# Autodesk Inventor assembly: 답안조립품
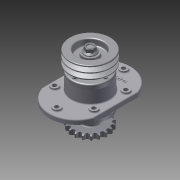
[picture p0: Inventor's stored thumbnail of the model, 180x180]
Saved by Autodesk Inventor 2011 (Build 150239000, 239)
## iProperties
Created: 2015-02
Part Number: 답안조립품
Document SubType Name: Assembly
Designer: Administrator
Author: Administrator
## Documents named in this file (11)
- C:\Documents and Settings\Administrator\바탕 화면\450207V1010\답안조립품.iam
- C:\Documents and Settings\Administrator\바탕 화면\450207V1010\본체.ipt
- C:\Documents and Settings\Administrator\바탕 화면\450207V1010\2-커버.ipt
- C:\Documents and Settings\Administrator\바탕 화면\450207V1010\3-축.ipt
- C:\Documents and Settings\Administrator\바탕 화면\450207V1010\11-키 6x6.ipt
- C:\Documents and Settings\Administrator\바탕 화면\450207V1010\4-V벨트풀리.ipt
- C:\Documents and Settings\Administrator\바탕 화면\450207V1010\9-M16-너트.ipt
- C:\Documents and Settings\Administrator\바탕 화면\450207V1010\5-체인 스프로킷.ipt
- C:\Documents and Settings\Administrator\바탕 화면\450207V1010\6-베어링 6206.ipt
- C:\Documents and Settings\Administrator\바탕 화면\450207V1010\10-M6.ipt
- C:\Documents and Settings\Administrator\바탕 화면\450207V1010\8-오일실 30x42.ipt
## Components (21 placed, 9 different names)
1. 2-커버:1
2. 2-커버:2
3. 3-축:1
4. 11-키 6x6:1 — 각도:3
5. 11-키 6x6:2 — 각도:2
6. 4-V벨트풀리:1
7. 9-M16 너트:1
8. 5-체인 스프로킷:1 — 각도:2
9. 9-M16 너트:2
10. 6-베어링 6206:1
11. 6-베어링 6206:2
12. 8-8-오일실 30x42:1
13. 8-8-오일실 30x42:2
14. 10-M6:1
15. 10-M6:3
16. 10-M6:4
17. 10-M6:5
18. 10-M6:2
19. 10-M6:6
20. 10-M6:7
21. 10-M6:8
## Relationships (2: Angle 2)
- 각도:2 [Angle]: 11-키 6x6:2 ↔ 5-체인 스프로킷:1
- 각도:3 [Angle]: 11-키 6x6:1
